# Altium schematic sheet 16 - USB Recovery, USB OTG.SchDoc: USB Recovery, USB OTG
size A3; PageSetup: Record=PageOptions¦CenterHorizontal=True¦CenterVertical=True¦PrintScale=0.70¦XCorrection=1.00¦YCorrection=1.00¦PrintKind=0¦BorderSize=5000000¦LeftOffset=0¦BottomOffset=0¦Orientation=2¦PaperLength=4200¦PaperWidth=2970¦Scale=100¦PaperSource=7¦PrintQuality=600¦MediaType=1¦DitherType=10¦PaperKind=A4¦PrintScaleMode=1; Author: Juan Anzola; SheetNumber: 16; SheetTotal: 21
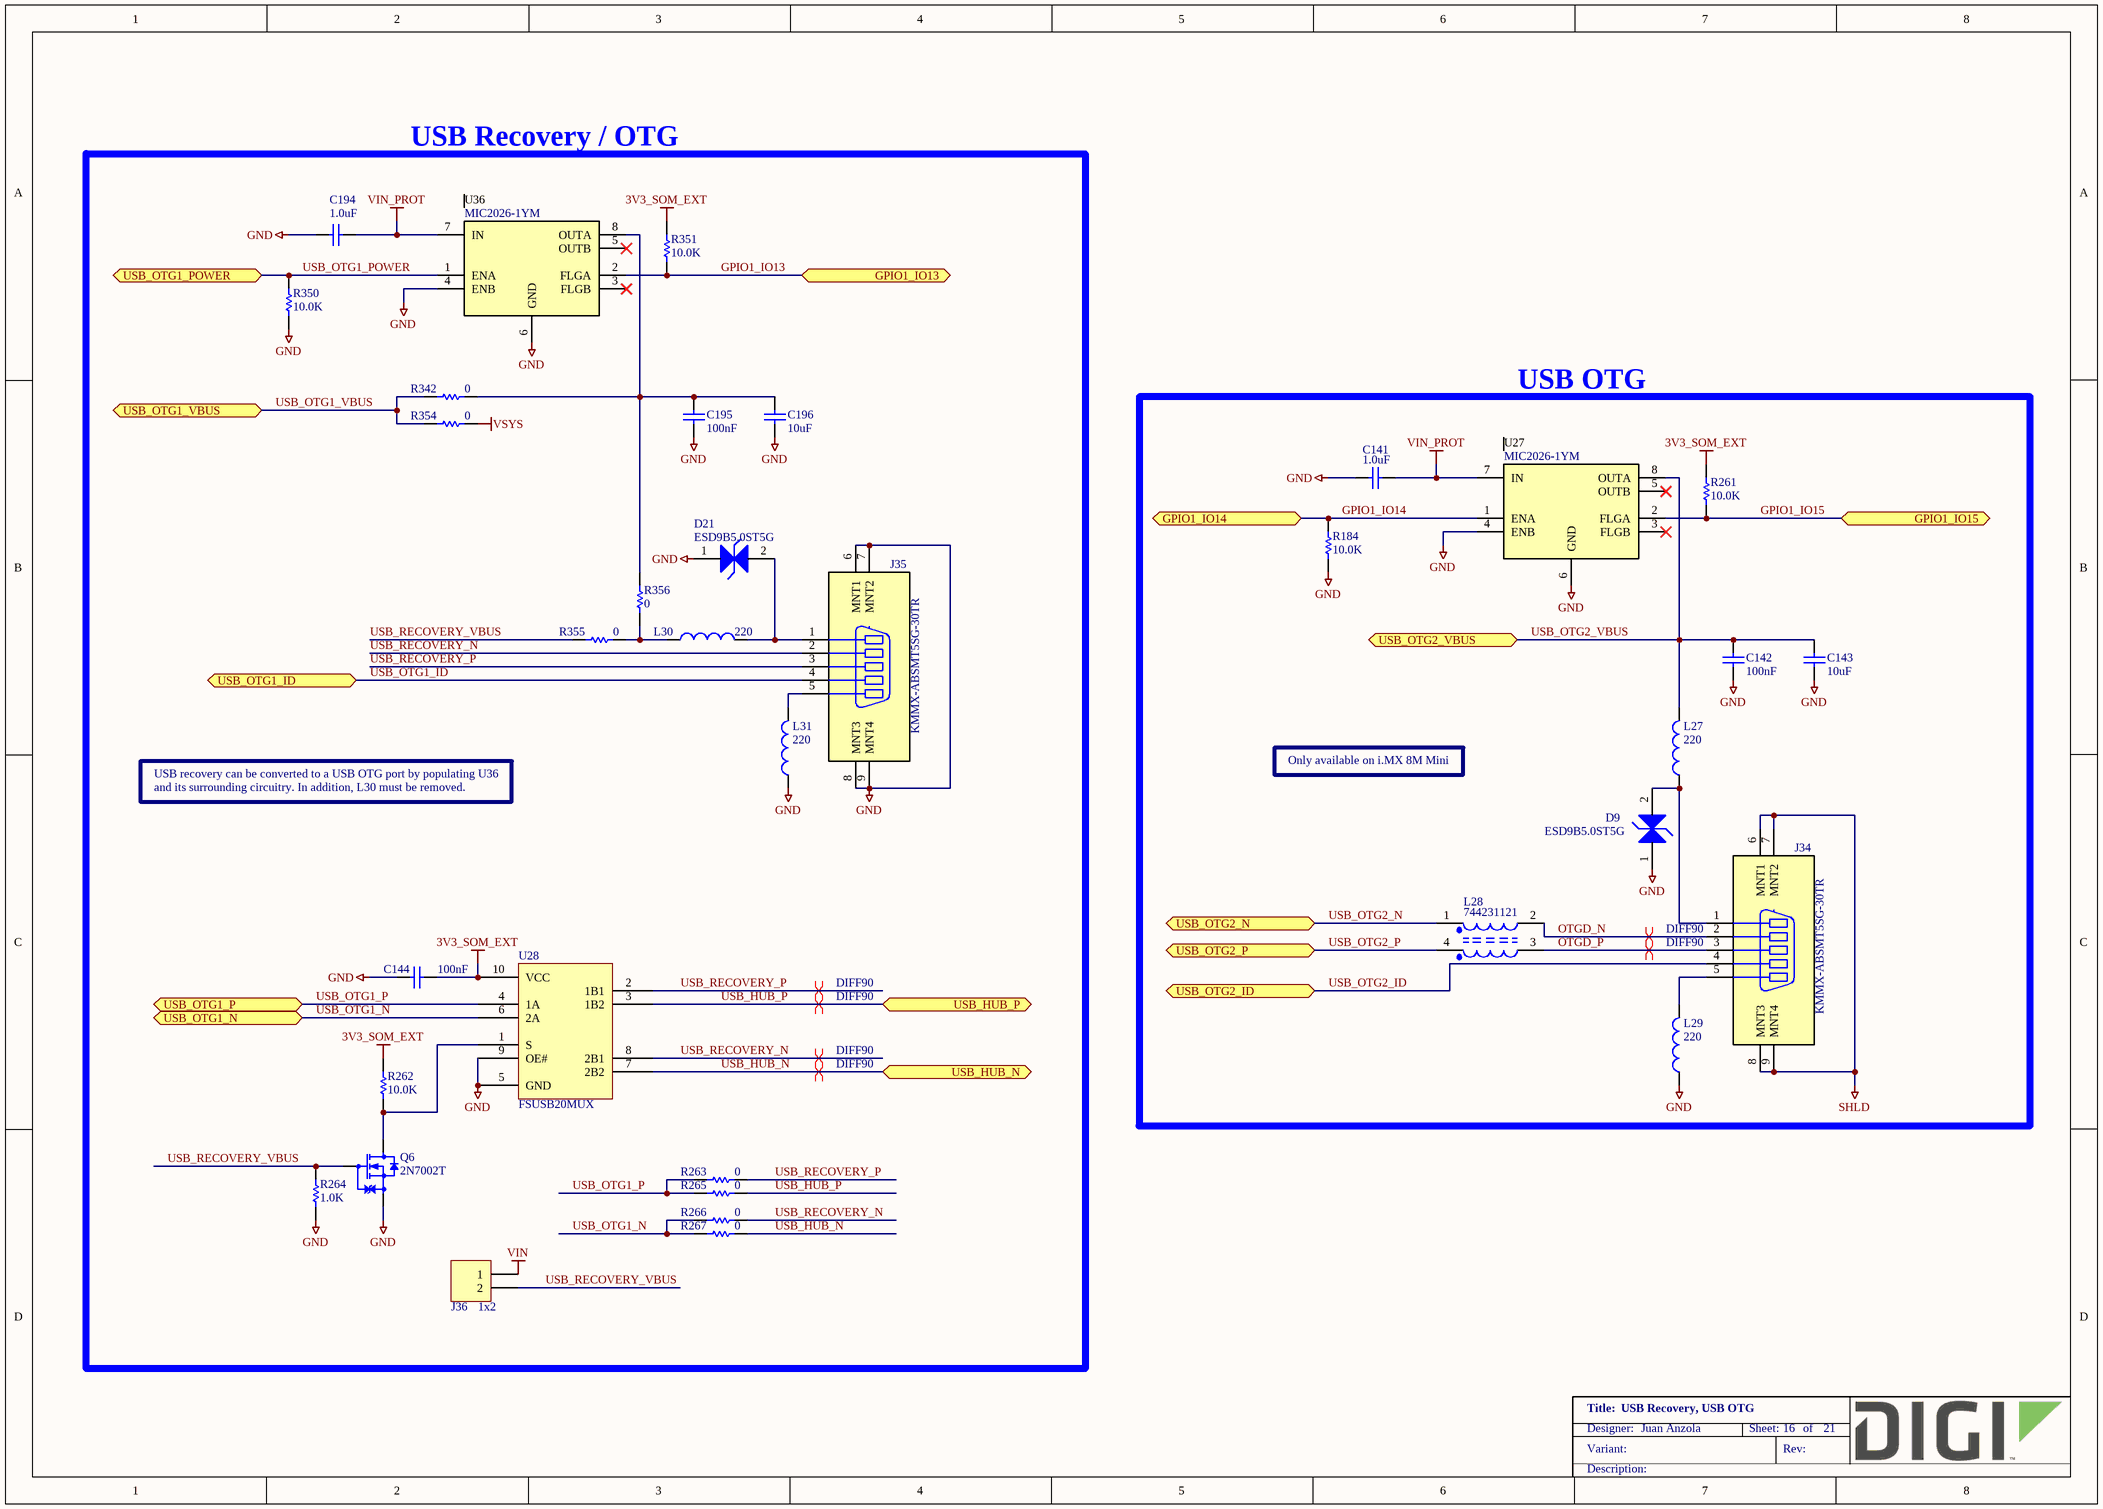
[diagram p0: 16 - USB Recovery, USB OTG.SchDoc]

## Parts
C141  1.0uF  [CAPC1005X55N]
C142  100nF  [CAPC1005X55N]
C143  10uF  [CAPC1005X55N]
C144  100nF  [CAPC1005X55N]
C194  1.0uF  [CAPC1005X55N]
C195  100nF  [CAPC1005X55N]
C196  10uF  [CAPC1005X55N]
D9  ESD9B5.0ST5G  [SODFL1006X43N12]
D21  ESD9B5.0ST5G  [SODFL1006X43N12]
J34  KMMX-ABSMT5SG-30TR  [KYCON_KMMX-ABSMT5]
J35  KMMX-ABSMT5SG-30TR  [KYCON_KMMX-ABSMT5]
J36  1x2  [FCI_68002-102HLF]
L27  220  [INDC2013X110N]
L28  744231121  [FIL_DLW21H]
L29  220  [INDC2013X110N]
L30  220  [INDC2013X110N]
L31  220  [INDC2013X110N]
Q6  2N7002T  [SOTFL50P160X80_GSD-3N]
R184  10.0K  [RESC1005X40N]
R261  10.0K  [RESC1005X40N]
R262  10.0K  [RESC1005X40N]
R263  0  [RESC1609X55N]
R264  1.0K  [RESC1005X40N]
R265  0  [RESC1609X55N]
R266  0  [RESC1609X55N]
R267  0  [RESC1609X55N]
R342  0  [RESC1005X40N]
R350  10.0K  [RESC1005X40N]
R351  10.0K  [RESC1005X40N]
R354  0  [RESC1005X40N]
R355  0  [RESC1609X55N]
R356  0  [RESC1609X55N]
U27  Manufacturer_Part_Number: MIC2026-1YM  [SOIC127P600X175-8N]  (hidden comment: MIC2026)
U28  FSUSB20MUX  [SOP50P490X110-10L30N]
U36  Manufacturer_Part_Number: MIC2026-1YM  [SOIC127P600X175-8N]  (hidden comment: MIC2026)

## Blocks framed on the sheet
USB Recovery / OTG: C144 C194-C196 D21 J35 J36 L30 L31 Q6 R262-R267 R342 R350 R351 R354-R356 U28 U36
USB OTG: C141-C143 D9 J34 L27-L29 R184 R261 U27

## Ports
GPIO1_IO13 (bidir), GPIO1_IO14 (bidir), GPIO1_IO15 (bidir), USB_HUB_N (bidir), USB_HUB_P (bidir), USB_OTG1_ID (bidir), USB_OTG1_N (bidir), USB_OTG1_P (bidir), USB_OTG1_POWER (bidir), USB_OTG1_VBUS (bidir), USB_OTG2_ID (bidir), USB_OTG2_N (bidir), USB_OTG2_P (bidir), USB_OTG2_VBUS (bidir)

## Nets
3V3_SOM_EXT: C144.1 R261.2 R262.1 R351.2 U28.10(VCC)
GND: C141.1 C142.1 C143.1 C144.2 C194.1 C195.1 C196.1 D9.1 D21.1 J35.6(MNT1) J35.7(MNT2) J35.8(MNT3) J35.9(MNT4) L29.1 L31.2 Q6.S R184.1 R264.1 R350.1 U27.4(ENB) U27.6(GND) U28.5(GND) U28.9(OE#) U36.4(ENB) U36.6(GND)
SHLD: J34.6(MNT1) J34.7(MNT2) J34.8(MNT3) J34.9(MNT4)
VIN: J36.1
VIN_PROT: C141.2 C194.2 U27.7(IN) U36.7(IN)
VSYS: R354.2
GPIO1_IO13: R351.1 U36.2(FLGA) ; port GPIO1_IO13
GPIO1_IO14: R184.2 U27.1(ENA) ; port GPIO1_IO14
GPIO1_IO15: R261.1 U27.2(FLGA) ; port GPIO1_IO15
OTGD_N: J34.2 L28.2
OTGD_P: J34.3 L28.3
USB_HUB_N: R267.2 U28.7(2B2) ; port USB_HUB_N
USB_HUB_P: R265.2 U28.3(1B2) ; port USB_HUB_P
USB_OTG1_ID: J35.4 ; port USB_OTG1_ID
USB_OTG1_N: R266.1 R267.1 U28.6(2A) ; port USB_OTG1_N
USB_OTG1_P: R263.1 R265.1 U28.4(1A) ; port USB_OTG1_P
USB_OTG1_POWER: R350.2 U36.1(ENA) ; port USB_OTG1_POWER
USB_OTG1_VBUS: R342.1 R354.1 ; port USB_OTG1_VBUS
USB_OTG2_ID: J34.4 ; port USB_OTG2_ID
USB_OTG2_N: L28.1 ; port USB_OTG2_N
USB_OTG2_P: L28.4 ; port USB_OTG2_P
USB_OTG2_VBUS: C142.2 C143.2 L27.2 U27.8(OUTA) ; port USB_OTG2_VBUS
USB_RECOVERY_N: J35.2 R266.2 U28.8(2B1)
USB_RECOVERY_P: J35.3 R263.2 U28.2(1B1)
USB_RECOVERY_VBUS: J36.2 Q6.G R264.2 R355.1
NetC195_2: C195.2 C196.2 R342.2 R356.2 U36.8(OUTA)
NetD9_2: D9.2 J34.1 L27.1
NetD21_2: D21.2 J35.1 L30.1
NetJ34_5: J34.5 L29.2
NetJ35_5: J35.5 L31.1
NetL30_2: L30.2 R355.2 R356.1
NetQ6_D: Q6.D R262.2 U28.1(S)

Not connected (* = marked no-connect by the designer): U27 3(FLGB)* 5(OUTB)*; U36 3(FLGB)* 5(OUTB)*

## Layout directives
differential pair; net class DIFF90: OTGD_N, OTGD_P, USB_HUB_N, USB_HUB_P, USB_RECOVERY_N, USB_RECOVERY_P

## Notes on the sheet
- USB recovery can be converted to a USB OTG port by populating U36
- Only available on i.MX 8M Mini
- and its surrounding circuitry. In addition, L30 must be removed.

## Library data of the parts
C141 = 1001167: CAP CER 1UF 10V 10% X5R 0402; Part_Type: Capacitor; Manufacturer: Murata; Manufacturer_Part_Number: GRM155R61A105KE15D; Digi_PN: 14050399; Component_Life_Cycle_State: Reviewed; Area: 0.95; Project: CCWMX6_SBC board
C142 C144 = 1000006: CAP 100nF 16V 10% X7R 0402; Part_Type: Capacitor; Manufacturer: Murata; Manufacturer_Part_Number: GRM155R71C104KA88D; Component_Life_Cycle_State: CAD Reviewed; Area: 0.95; Project: KITT; Tolerance: 10; Digi_PN: 14050552
C143 = 1001168: CAP CER 10UF 10V 20% X5R 0402; Part_Type: Capacitor; Manufacturer: Samsung; Manufacturer_Part_Number: CL05A106MP5NUNC; Digi_PN: 14050689; Component_Life_Cycle_State: Reviewed; Area: 0.95; Project: CCWMX6_SBC board
C194 = 1001167: CAP CER 1UF 10V 10% X5R 0402; Part_Type: Capacitor; Manufacturer: Murata; Manufacturer_Part_Number: GRM155R61A105KE15D; Digi_PN: 14050399; Component_Life_Cycle_State: Reviewed; Area: 0,95
C195 = 1000006: CAP 100nF 16V 10% X7R 0402; Part_Type: Capacitor; Manufacturer: Murata; Manufacturer_Part_Number: GRM155R71C104KA88D; Digi_PN: 14050552; Component_Life_Cycle_State: CAD Reviewed; Area: 0,95; Tolerance: 10
C196 = 1001168: CAP CER 10UF 10V 20% X5R 0402; Part_Type: Capacitor; Manufacturer: Samsung; Manufacturer_Part_Number: CL05A106MP5NUNC; Digi_PN: 14050689; Component_Life_Cycle_State: Reviewed; Area: 0,95
D9 D21 = 1001264: TVS DIODE 5VWM SOD923; Part_Type: Diodes; Manufacturer: On Semiconductor; Digi_PN: 17050587; Component_Life_Cycle_State: Reviewed; Area: 1.5; Project: CCWMX6_SBC board
J34 = 1001117: CONN RECEPT MICRO-USB TYPE AB R/A; Part_Type: Connector; Manufacturer: KYCON; Digi_PN: 18000401; Component_Life_Cycle_State: Reviewed; Area: 40; Project: CCWMX6_SBC board
J35 = 1001117: CONN RECEPT MICRO-USB TYPE AB R/A; Part_Type: Connector; Manufacturer: KYCON; Digi_PN: 18000401; Component_Life_Cycle_State: Reviewed; Area: 40
J36 = 1001128: CONN HEADER 2POS .100" SGL GOLD; Part_Type: Connector; Manufacturer: Samtec; Manufacturer_Part_Number: TSW-102-07-G-S; Digi_PN: 00120002; Component_Life_Cycle_State: Reviewed; Area: 12,9032
L27 L29 L30 = 1001174: FERRITE BEAD 220 OHM 2.0A 0805; Manufacturer: Wurth Electronics Inc; Manufacturer_Part_Number: 742792022; Digi_PN: 21000146; Component_Life_Cycle_State: Reviewed; Area: 4.24; Project: CCWMX6_SBC board
L28 = 1001173: CHOKE COM MODE 120 OHM .37A; Part_Type: Inductor; Manufacturer: Wurth Electronics Inc; Digi_PN: 21000143; Component_Life_Cycle_State: Reviewed; Area: 2.4; Project: CCWMX6_SBC board
L31 = 1001174: FERRITE BEAD 220 OHM 2.0A 0805; Manufacturer: Wurth Electronics Inc; Manufacturer_Part_Number: 742792022; Digi_PN: 21000146; Component_Life_Cycle_State: Reviewed; Area: 4,24
Q6 = 1000715: MOSFET N-CH 60V 115MA SOT-523F; Part_Type: Transistor; Manufacturer: Fairchild Semiconductor; Note: 17050841 = Digi No. for GE WDNU; Digi_PN: 17050797; Component_Life_Cycle_State: CAD Reviewed; Area: 3,06; Project: SmartMeter2
R184 R261 R262 = 1000537: RES 10.0K OHM 1/10W 1% 0402 SMD; Part_Type: Resistor; Manufacturer: Panasonic - ECG; Manufacturer_Part_Number: ERJ-2RKF1002X; Component_Life_Cycle_State: CAD Reviewed; Area: 0.95; Project: KITT; Power_WV_SRF: 100; Digi_PN: 13051084
R263 R265-R267 R355 R356 = 1000208: RES 0.0 OHM 1/10W 0603; Part_Type: Resistor; Manufacturer: Panasonic - ECG; Manufacturer_Part_Number: ERJ-3GEY0R00V; Note: 13051103 = Digi No. for GE WDNU; Digi_PN: 13050568; Component_Life_Cycle_State: Reviewed; Area: 2,5; Voltage: 75V
R264 = 1000079: RES 1.00K OHM 1/10W 1% 0402 SMD; Part_Type: Resistor; Manufacturer: Panasonic - ECG; Manufacturer_Part_Number: ERJ-2RKF1001X; Digi_PN: 13051085; Component_Life_Cycle_State: Proven; Area: 0,95; Project: Adjustable Foundation; Power_WV_SRF: 10
R342 R354 = 1000076: RES 0.0 OHM 1/10W 0402 SMD; Part_Type: Resistor; Manufacturer: Panasonic - ECG; Manufacturer_Part_Number: ERJ-2GE0R00X; Digi_PN: 13050387; Component_Life_Cycle_State: Proven; Area: 0,95; Power_WV_SRF: 10
R350 R351 = 1000537: RES 10.0K OHM 1/10W 1% 0402 SMD; Part_Type: Resistor; Manufacturer: Panasonic - ECG; Manufacturer_Part_Number: ERJ-2RKF1002X; Digi_PN: 13051084; Component_Life_Cycle_State: CAD Reviewed; Area: 0,95; Power_WV_SRF: 100
U27 U36 = 1001143: IC SW DISTRIBUTION 2CHAN 8SOIC; Manufacturer: Micrel; Digi_PN: 16051879; Component_Life_Cycle_State: Reviewed; Area: 29.58; Project: CCWMX6_SBC board
U28 = 1002730: IC USB SWITCH DUAL 2X1 10MSOP; Manufacturer: On Semiconductor; Digi_PN: 16051919; Component_Life_Cycle_State: Pending; Area: 17,58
